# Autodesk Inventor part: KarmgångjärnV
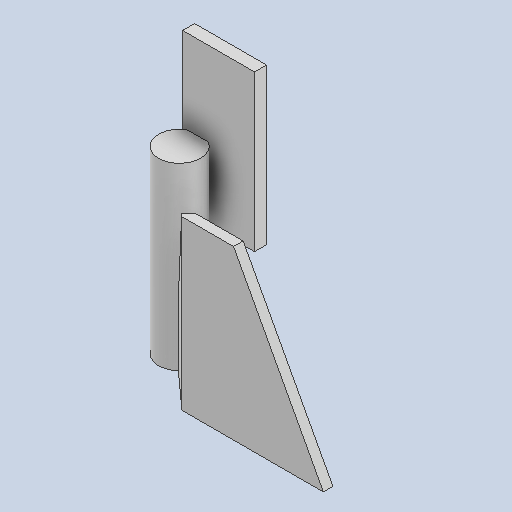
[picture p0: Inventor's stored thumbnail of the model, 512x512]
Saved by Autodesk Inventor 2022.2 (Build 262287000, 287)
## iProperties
Created: 2019-06
Part Number: KarmgångjärnV
Material: Generic
Document SubType Name: Modeling
Designer: cl
Density: 1 g/cm^3
Appearance: Default
Author: cl
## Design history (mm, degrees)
sketch "Sketch1"
  geometry: L1 (0, 8)-(115, 8); L2 (118.071, 0)-(0, 0); L3 (0, 0)-(0, 8); L4 (115, 8)-(142.016, 32.325); L5 (115, 8)-(126.561, 8); L6 (118.071, 0)-(147.369, 26.38); L7 (142.016, 32.325)-(147.369, 26.38); L8 (0, 0)-(250, 0); L9 (0, -8)-(115, -8); L10 (115, -8)-(142.016, -32.325); L11 (118.071, 0)-(147.369, -26.38); L12 (142.016, -32.325)-(147.369, -26.38); L13 (0, 0)-(0, -8); C1 r 17.5 at (160, 40); C2 r 17.5 at (160, -40); 3 further points
  constraints: 26 end point, 5 symmetric about line, 3 coincident, 2 centre point, 2 horizontal, 2 parallel, 1 perpendicular, 1 point on line, 1 vertical, 1 other
  dimensions: "d0" = 35 diameter of C1; "d1" = 40 vertical distance of point (0, 0) C1.centre; "d2" = 160 horizontal distance of point (0, 0) C1.centre; "d3" = 42 deg angle of L5 L4; "d4" = 8 distance between parallel lines of L4 L6; "d5" = 8 distance between parallel lines of L1 L2; "d6" = 115 horizontal distance of point (0, 0) L1.end; "d7" = 1 distance edge to line of C1 L7; "d8" = 90 deg angle of L4 L7; "d9" = 27.76238 distance from line of L5.end L7; "d10" = 250 distance of L2.end L8.end
extrude "Extrusion1" new body sketch "Sketch1" distance "d11" = 140; taper "d12" = 0 deg
thicken "Thicken1" dims "d13" = 10, "d14" = 10
chamfer "Chamfer1" distance "d15" = 75; stored, may be unused: second distance "d16" = 140, angle "d17" = 45 deg
sketch "Sketch2"
  geometry: L1 (-36.354, 0)-(-36.354, 140) reference; L2 (-36.354, 140)-(0, 56); L3 (0, 0)-(0, 140) reference; L4 (-36.354, 0)-(0, 0) reference; L5 (0, 140)-(-39.425, 140) reference; L6 (-36.354, 140)-(0, 140); L7 (0, 140)-(0, 56); L8 (1, 0)-(1, 150) reference; 1 further point
  constraints: 6 end point, 1 horizontal, 1 parallel, 1 point on line
  dimensions: "d18" = 56 distance from line of L4 L2.end
extrude "Extrusion2" cut sketch "Sketch2" extent not by distance; stored distance "d19" = 0; taper "d20" = 0 deg
workplane "Work Plane1"
sketch "Sketch4"
  geometry: L1 (112.5, 220)-(172.5, 220); L2 (172.5, 220)-(172.5, 90); L3 (172.5, 90)-(112.5, 90); L4 (112.5, 90)-(112.5, 220); L5 (177.5, 150)-(142.5, 150) reference; 1 further point
  constraints: 8 end point, 2 parallel, 1 horizontal, 1 perpendicular
  dimensions: "d27" = 60 distance of L2.end L3.end; "d28" = 130 distance of L1.end L2.end; "d30" = 70 distance between parallel lines of L1 L5; "d33" = 5 distance from line of L5.start L2
extrude "Extrusion3" join sketch "Sketch4" distance "d31" = 10; taper "d32" = 0 deg
body "Solid1"
other parameters: "d26" = 57
